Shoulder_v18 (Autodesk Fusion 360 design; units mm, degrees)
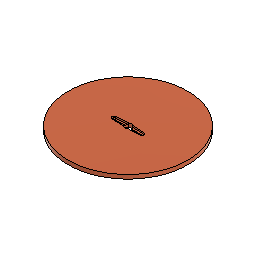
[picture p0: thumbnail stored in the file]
sketch "Sketch1" plane through (0, 0, 0) normal (0, 0, 1) x axis (1, 0, 0)
  line L1 (2.2091, 2.65) -> (14.1591, 1.997)
  line L2 (-2.2091, -2.65) -> (-14.1591, -1.997)
  line L3 (14.1591, -1.997) -> (2.2091, -2.65)
  line L4 (-14.1591, 1.997) -> (-2.2091, 2.65)
  circle C1 centre (0, 0) radius 60
  circle C2 centre (10.45, 0) radius 0.6
  circle C3 centre (6.45, 0) radius 0.6
  circle C4 centre (-14.45, 0) radius 0.6
  circle C5 centre (-8.45, 0) radius 0.6
  circle C6 centre (-12.45, 0) radius 0.6
  circle C7 centre (8.45, 0) radius 0.6
  circle C8 centre (-10.45, 0) radius 0.6
  arc A1 centre (-14.05, 0) radius 2 clockwise from (-14.1591, -1.997) to (-14.1591, 1.997)
  arc A2 centre (0, 0) radius 3.45 clockwise from (-2.2091, 2.65) to (2.2091, 2.65)
  circle C9 centre (4.45, 0) radius 0.6
  circle C10 centre (12.45, 0) radius 0.6
  arc A3 centre (14.05, 0) radius 2 clockwise from (14.1591, 1.997) to (14.1591, -1.997)
  arc A4 centre (0, 0) radius 3.45 clockwise from (2.2091, -2.65) to (-2.2091, -2.65)
  circle C11 centre (0, 0) radius 2.3
  circle C12 centre (-4.45, 0) radius 0.6
  circle C13 centre (14.45, 0) radius 0.6
  circle C14 centre (-6.45, 0) radius 0.6
  circle C15 centre (0, 0) radius 3.55
  point P1 (0, 0)
  point P2 (0, 0)
  point P27 (0, 0)
  coincident P1 P2
  coincident P1 P27
  dimension "d1" diameter C1 = 120
  dimension "d34" diameter C15 = 7.1
extrude "Extrude1" new body sketch "Sketch1" profile of C1 L1 A1 A2 L2 L3 L4 A3 A4 along normal blind 4
sketch "Sketch2" plane through (0, 0, 4) normal (0, 0, 1) x axis (-1, 0, 0)
  line L1 (-7, -13.9) -> (7, -13.9)
  line L2 (-7, 13.9) -> (-7, -13.9)
  line L3 (7, 13.9) -> (-7, 13.9)
  line L4 (7, -13.9) -> (7, 13.9)
  line L5 (-7, 13.9) -> (7, -13.9)
  line L6 (7, 13.9) -> (-7, -13.9)
  line L7 (14.1591, 1.997) -> (2.2091, 2.65)
  line L8 (2.2091, -2.65) -> (14.1591, -1.997)
  line L9 (-14.1591, -1.997) -> (-2.2091, -2.65)
  line L10 (-2.2091, 2.65) -> (-14.1591, 1.997)
  circle C1 centre (0, 0) radius 60
  arc A1 centre (0, 0) radius 3.45 clockwise from (-2.2091, 2.65) to (2.2091, 2.65)
  arc A2 centre (14.05, 0) radius 2 clockwise from (14.1591, 1.997) to (14.1591, -1.997)
  arc A3 centre (0, 0) radius 3.45 clockwise from (2.2091, -2.65) to (-2.2091, -2.65)
  arc A4 centre (-14.05, 0) radius 2 clockwise from (-14.1591, -1.997) to (-14.1591, 1.997)
  point P7 (0, 0)
  point P2 (0, 0)
  point P5 (-7, 13.9)
  point P6 (7, 13.9)
  point P4 (-7, -13.9)
  horizontal L1
  perpendicular L1 L2
  parallel L1 L3
  parallel L2 L4
  coincident L5 P7
  coincident L6 P7
  coincident P2 P7
  dimension "d18" distance P5 P6 = 14
  dimension "d19" distance P4 P5 = 27.8
extrude "Extrude3" add sketch "Sketch1" profile of C2 C3 C4 C5 L1 C6 C7 C8 A1 L2 C9 L3 L4 C10 A3 C12 C13 C14 C15 along normal blind 2.4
